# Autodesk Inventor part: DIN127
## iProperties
Shininess: 25.0
Length Units: 11269
Angle Units: 11279
Time Units: 11290
Mass Units: 11283
Length Display Precision: 3
Angle Display Precision: 2
Compacted: True
Created: 2001-01
Part Number: DIN127
Material: Steel
Description: Spring washer M10
Vendor: DIN 125
Document SubType Name: Modeling
Designer: Robbert Osinga
Density: 0.0
Volumn: 0.0
Area: 0.0
PropertySet Name: Model Information
Control State: 0
Master: False
Checked Out: False
Checked Out By: ?
Author: Robbert Osinga
Revision Number: 0
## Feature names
1. Extrusion1
2. Extrusion2
